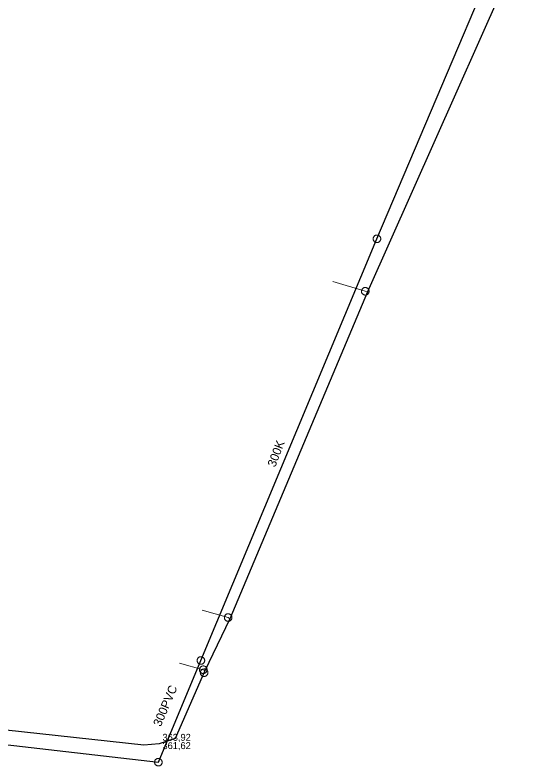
# Model space of a CAD drawing. Extents: x -741806 to -738704, y -1059275 to -1055387.
# Drawn here: x -740928.6 to -740869.8, y -1058224.8 to -1058138 of the extents above; entities that cross this region are included whole.
import ezdxf

# ---------------------------------------------------------------- set-up
doc = ezdxf.new("R2010")
doc.units = 0
doc.header["$LTSCALE"] = 0.4
for name, color, linetype, lineweight in [('2', 7, 'Continuous', 25), ('21', 7, 'Continuous', 13), ('3', 7, 'Continuous', 13), ('51', 7, 'Continuous', 13), ('52', 7, 'Continuous', 25), ('6', 7, 'Continuous', 13)]:
    doc.layers.add(name, color=color, linetype=linetype, lineweight=lineweight)
doc.layers.add('5', color=7, linetype='Continuous')

msp = doc.modelspace()

# ---------------------------------------------------------------- linework, layer by layer
at = {"layer": '2'}
for points in [[(-740907.18, -1058212.62), (-740886.85, -1058163.899), (-740866.18, -1058115.19), (-740843.879, -1058067.21), (-740824.89, -1058051.27)], [(-740986.62, -1058215.929), (-740978.449, -1058216.909), (-740964.91, -1058218.3), (-740912.09, -1058224.37), (-740907.18, -1058212.62)]]:
    msp.add_lwpolyline(points, dxfattribs=at)
at = {"layer": '21'}
for points in [[(-740887.96, -1058170.041), (-740888.199, -1058169.96), (-740891.956, -1058168.844)], [(-740903.829, -1058207.8), (-740904.028, -1058207.656), (-740907.026, -1058206.804)], [(-740906.688, -1058213.771), (-740906.906, -1058213.688), (-740909.64, -1058212.922)]]:
    msp.add_lwpolyline(points, dxfattribs=at)
at = {"layer": '3'}
for points in [[(-740886.689, -1058163.491), (-740886.732, -1058163.477), (-740886.776, -1058163.467), (-740886.822, -1058163.462), (-740886.867, -1058163.462), (-740886.913, -1058163.466), (-740886.959, -1058163.475), (-740887.002, -1058163.489), (-740887.044, -1058163.507), (-740887.083, -1058163.53), (-740887.121, -1058163.557), (-740887.155, -1058163.587), (-740887.187, -1058163.621), (-740887.213, -1058163.658), (-740887.237, -1058163.697), (-740887.256, -1058163.739), (-740887.271, -1058163.782), (-740887.28, -1058163.827), (-740887.286, -1058163.872), (-740887.285, -1058163.918), (-740887.281, -1058163.964), (-740887.272, -1058164.009), (-740887.258, -1058164.051), (-740887.24, -1058164.094), (-740887.218, -1058164.134), (-740887.191, -1058164.172), (-740887.16, -1058164.205), (-740887.127, -1058164.236), (-740887.089, -1058164.264), (-740887.05, -1058164.287), (-740887.008, -1058164.306), (-740886.965, -1058164.32), (-740886.921, -1058164.33), (-740886.875, -1058164.336), (-740886.828, -1058164.336), (-740886.784, -1058164.332), (-740886.738, -1058164.323), (-740886.695, -1058164.308), (-740886.653, -1058164.29), (-740886.614, -1058164.267), (-740886.576, -1058164.241), (-740886.542, -1058164.211), (-740886.51, -1058164.177), (-740886.483, -1058164.14), (-740886.46, -1058164.101), (-740886.441, -1058164.059), (-740886.426, -1058164.015), (-740886.416, -1058163.971), (-740886.412, -1058163.926), (-740886.412, -1058163.879), (-740886.416, -1058163.834), (-740886.426, -1058163.789), (-740886.438, -1058163.745), (-740886.457, -1058163.703), (-740886.479, -1058163.664), (-740886.507, -1058163.626), (-740886.537, -1058163.592), (-740886.57, -1058163.561), (-740886.608, -1058163.534), (-740886.647, -1058163.511), (-740886.688, -1058163.491)], [(-740907.019, -1058212.212), (-740907.062, -1058212.198), (-740907.106, -1058212.188), (-740907.152, -1058212.183), (-740907.197, -1058212.183), (-740907.243, -1058212.187), (-740907.289, -1058212.196), (-740907.332, -1058212.21), (-740907.374, -1058212.228), (-740907.413, -1058212.251), (-740907.451, -1058212.278), (-740907.485, -1058212.308), (-740907.517, -1058212.342), (-740907.543, -1058212.379), (-740907.567, -1058212.418), (-740907.586, -1058212.46), (-740907.601, -1058212.503), (-740907.61, -1058212.548), (-740907.616, -1058212.593), (-740907.615, -1058212.639), (-740907.611, -1058212.685), (-740907.602, -1058212.73), (-740907.588, -1058212.772), (-740907.57, -1058212.815), (-740907.548, -1058212.855), (-740907.521, -1058212.893), (-740907.49, -1058212.926), (-740907.457, -1058212.957), (-740907.419, -1058212.985), (-740907.38, -1058213.008), (-740907.338, -1058213.027), (-740907.295, -1058213.041), (-740907.251, -1058213.051), (-740907.205, -1058213.057), (-740907.158, -1058213.057), (-740907.114, -1058213.053), (-740907.068, -1058213.044), (-740907.025, -1058213.029), (-740906.983, -1058213.011), (-740906.944, -1058212.988), (-740906.906, -1058212.962), (-740906.872, -1058212.932), (-740906.84, -1058212.898), (-740906.813, -1058212.861), (-740906.79, -1058212.822), (-740906.771, -1058212.78), (-740906.756, -1058212.736), (-740906.746, -1058212.692), (-740906.742, -1058212.647), (-740906.742, -1058212.6), (-740906.746, -1058212.555), (-740906.756, -1058212.51), (-740906.768, -1058212.466), (-740906.787, -1058212.424), (-740906.809, -1058212.385), (-740906.837, -1058212.347), (-740906.867, -1058212.313), (-740906.9, -1058212.282), (-740906.938, -1058212.255), (-740906.977, -1058212.232), (-740907.018, -1058212.212)], [(-740911.654, -1058224.42), (-740911.652, -1058224.375), (-740911.654, -1058224.329), (-740911.661, -1058224.283), (-740911.672, -1058224.24), (-740911.688, -1058224.197), (-740911.709, -1058224.155), (-740911.733, -1058224.117), (-740911.761, -1058224.081), (-740911.794, -1058224.049), (-740911.829, -1058224.019), (-740911.867, -1058223.994), (-740911.908, -1058223.972), (-740911.95, -1058223.956), (-740911.994, -1058223.943), (-740912.04, -1058223.936), (-740912.086, -1058223.933), (-740912.131, -1058223.935), (-740912.176, -1058223.941), (-740912.221, -1058223.953), (-740912.264, -1058223.969), (-740912.305, -1058223.99), (-740912.343, -1058224.014), (-740912.379, -1058224.043), (-740912.412, -1058224.074), (-740912.441, -1058224.11), (-740912.466, -1058224.149), (-740912.487, -1058224.188), (-740912.504, -1058224.232), (-740912.517, -1058224.276), (-740912.524, -1058224.321), (-740912.527, -1058224.366), (-740912.525, -1058224.412), (-740912.518, -1058224.458), (-740912.506, -1058224.502), (-740912.491, -1058224.544), (-740912.471, -1058224.586), (-740912.446, -1058224.624), (-740912.417, -1058224.661), (-740912.385, -1058224.692), (-740912.35, -1058224.722), (-740912.312, -1058224.747), (-740912.271, -1058224.769), (-740912.229, -1058224.786), (-740912.185, -1058224.798), (-740912.14, -1058224.805), (-740912.094, -1058224.808), (-740912.048, -1058224.807), (-740912.003, -1058224.8), (-740911.958, -1058224.788), (-740911.915, -1058224.772), (-740911.875, -1058224.751), (-740911.836, -1058224.727), (-740911.8, -1058224.698), (-740911.767, -1058224.667), (-740911.738, -1058224.631), (-740911.712, -1058224.592), (-740911.692, -1058224.553), (-740911.675, -1058224.509), (-740911.663, -1058224.465), (-740911.655, -1058224.421)]]:
    msp.add_lwpolyline(points, dxfattribs=at)
at = {"layer": '51'}
for points in [[(-740888.612, -1058169.819), (-740888.625, -1058169.862), (-740888.633, -1058169.907), (-740888.636, -1058169.953), (-740888.634, -1058169.998), (-740888.627, -1058170.044), (-740888.616, -1058170.089), (-740888.6, -1058170.131), (-740888.58, -1058170.173), (-740888.555, -1058170.211), (-740888.527, -1058170.247), (-740888.495, -1058170.28), (-740888.46, -1058170.31), (-740888.422, -1058170.335), (-740888.382, -1058170.356), (-740888.339, -1058170.373), (-740888.294, -1058170.386), (-740888.25, -1058170.394), (-740888.204, -1058170.396), (-740888.158, -1058170.394), (-740888.112, -1058170.387), (-740888.068, -1058170.376), (-740888.025, -1058170.361), (-740887.984, -1058170.34), (-740887.946, -1058170.316), (-740887.909, -1058170.287), (-740887.876, -1058170.255), (-740887.848, -1058170.22), (-740887.822, -1058170.182), (-740887.801, -1058170.141), (-740887.783, -1058170.099), (-740887.772, -1058170.055), (-740887.764, -1058170.01), (-740887.761, -1058169.964), (-740887.762, -1058169.919), (-740887.769, -1058169.873), (-740887.78, -1058169.828), (-740887.796, -1058169.786), (-740887.816, -1058169.744), (-740887.841, -1058169.706), (-740887.869, -1058169.67), (-740887.901, -1058169.637), (-740887.937, -1058169.607), (-740887.975, -1058169.583), (-740888.015, -1058169.561), (-740888.058, -1058169.544), (-740888.102, -1058169.531), (-740888.147, -1058169.524), (-740888.192, -1058169.521), (-740888.239, -1058169.523), (-740888.284, -1058169.53), (-740888.328, -1058169.541), (-740888.371, -1058169.556), (-740888.412, -1058169.577), (-740888.451, -1058169.601), (-740888.487, -1058169.63), (-740888.52, -1058169.662), (-740888.549, -1058169.697), (-740888.574, -1058169.735), (-740888.596, -1058169.776), (-740888.612, -1058169.818)], [(-740904.19, -1058208.061), (-740904.147, -1058208.076), (-740904.103, -1058208.086), (-740904.057, -1058208.092), (-740904.012, -1058208.092), (-740903.966, -1058208.088), (-740903.92, -1058208.079), (-740903.877, -1058208.065), (-740903.834, -1058208.048), (-740903.795, -1058208.025), (-740903.758, -1058207.999), (-740903.723, -1058207.968), (-740903.691, -1058207.935), (-740903.664, -1058207.898), (-740903.641, -1058207.859), (-740903.622, -1058207.817), (-740903.607, -1058207.774), (-740903.597, -1058207.729), (-740903.592, -1058207.684), (-740903.591, -1058207.638), (-740903.596, -1058207.592), (-740903.605, -1058207.547), (-740903.618, -1058207.503), (-740903.636, -1058207.461), (-740903.658, -1058207.422), (-740903.685, -1058207.384), (-740903.715, -1058207.349), (-740903.749, -1058207.319), (-740903.786, -1058207.291), (-740903.825, -1058207.268), (-740903.867, -1058207.248), (-740903.91, -1058207.234), (-740903.954, -1058207.224), (-740904, -1058207.219), (-740904.045, -1058207.218), (-740904.091, -1058207.222), (-740904.137, -1058207.231), (-740904.18, -1058207.245), (-740904.222, -1058207.262), (-740904.262, -1058207.286), (-740904.299, -1058207.312), (-740904.334, -1058207.342), (-740904.365, -1058207.376), (-740904.392, -1058207.412), (-740904.416, -1058207.451), (-740904.435, -1058207.493), (-740904.45, -1058207.537), (-740904.459, -1058207.581), (-740904.465, -1058207.626), (-740904.465, -1058207.673), (-740904.461, -1058207.718), (-740904.452, -1058207.763), (-740904.439, -1058207.807), (-740904.42, -1058207.849), (-740904.399, -1058207.889), (-740904.372, -1058207.926), (-740904.341, -1058207.961), (-740904.308, -1058207.991), (-740904.271, -1058208.019), (-740904.232, -1058208.042), (-740904.191, -1058208.061)], [(-740907.312, -1058213.527), (-740907.327, -1058213.57), (-740907.337, -1058213.614), (-740907.342, -1058213.66), (-740907.342, -1058213.705), (-740907.338, -1058213.751), (-740907.329, -1058213.796), (-740907.315, -1058213.84), (-740907.297, -1058213.882), (-740907.274, -1058213.921), (-740907.248, -1058213.959), (-740907.217, -1058213.993), (-740907.183, -1058214.025), (-740907.147, -1058214.052), (-740907.108, -1058214.075), (-740907.065, -1058214.094), (-740907.022, -1058214.109), (-740906.977, -1058214.119), (-740906.932, -1058214.124), (-740906.886, -1058214.124), (-740906.84, -1058214.119), (-740906.796, -1058214.11), (-740906.752, -1058214.097), (-740906.71, -1058214.078), (-740906.67, -1058214.056), (-740906.633, -1058214.029), (-740906.598, -1058213.998), (-740906.568, -1058213.965), (-740906.54, -1058213.928), (-740906.517, -1058213.888), (-740906.497, -1058213.847), (-740906.484, -1058213.804), (-740906.474, -1058213.759), (-740906.468, -1058213.713), (-740906.468, -1058213.668), (-740906.472, -1058213.622), (-740906.481, -1058213.577), (-740906.496, -1058213.533), (-740906.513, -1058213.491), (-740906.536, -1058213.452), (-740906.563, -1058213.415), (-740906.593, -1058213.38), (-740906.627, -1058213.349), (-740906.664, -1058213.322), (-740906.703, -1058213.298), (-740906.745, -1058213.279), (-740906.788, -1058213.265), (-740906.833, -1058213.255), (-740906.878, -1058213.25), (-740906.924, -1058213.25), (-740906.97, -1058213.254), (-740907.015, -1058213.263), (-740907.058, -1058213.276), (-740907.1, -1058213.295), (-740907.14, -1058213.317), (-740907.178, -1058213.344), (-740907.212, -1058213.375), (-740907.243, -1058213.408), (-740907.27, -1058213.446), (-740907.293, -1058213.485), (-740907.312, -1058213.526)], [(-740906.983, -1058214.434), (-740906.941, -1058214.45), (-740906.897, -1058214.461), (-740906.851, -1058214.468), (-740906.807, -1058214.471), (-740906.761, -1058214.468), (-740906.715, -1058214.461), (-740906.671, -1058214.448), (-740906.628, -1058214.432), (-740906.588, -1058214.41), (-740906.55, -1058214.386), (-740906.514, -1058214.357), (-740906.481, -1058214.324), (-740906.453, -1058214.289), (-740906.428, -1058214.25), (-740906.408, -1058214.209), (-740906.391, -1058214.166), (-740906.379, -1058214.122), (-740906.373, -1058214.077), (-740906.371, -1058214.031), (-740906.374, -1058213.985), (-740906.381, -1058213.94), (-740906.393, -1058213.895), (-740906.41, -1058213.853), (-740906.43, -1058213.812), (-740906.456, -1058213.774), (-740906.485, -1058213.738), (-740906.517, -1058213.707), (-740906.554, -1058213.677), (-740906.592, -1058213.653), (-740906.633, -1058213.632), (-740906.675, -1058213.616), (-740906.719, -1058213.605), (-740906.765, -1058213.598), (-740906.81, -1058213.595), (-740906.856, -1058213.598), (-740906.902, -1058213.605), (-740906.946, -1058213.618), (-740906.989, -1058213.634), (-740907.029, -1058213.656), (-740907.067, -1058213.681), (-740907.103, -1058213.71), (-740907.136, -1058213.742), (-740907.163, -1058213.778), (-740907.189, -1058213.816), (-740907.209, -1058213.857), (-740907.226, -1058213.9), (-740907.236, -1058213.945), (-740907.244, -1058213.989), (-740907.246, -1058214.036), (-740907.243, -1058214.082), (-740907.235, -1058214.126), (-740907.224, -1058214.171), (-740907.207, -1058214.213), (-740907.186, -1058214.254), (-740907.161, -1058214.292), (-740907.132, -1058214.328), (-740907.1, -1058214.36), (-740907.063, -1058214.389), (-740907.025, -1058214.413), (-740906.984, -1058214.433)]]:
    msp.add_lwpolyline(points, dxfattribs=at)
at = {"layer": '52'}
for points in [[(-740626.537, -1058069.271), (-740626.965, -1058069.033), (-740656.548, -1058067.382), (-740672.59, -1058065.485), (-740708.822, -1058062.591), (-740710.671, -1058062.095), (-740751.42, -1058058.46), (-740773.993, -1058056.467), (-740779.522, -1058055.831), (-740794.666, -1058054.688), (-740823.883, -1058052.338), (-740835.024, -1058060.166), (-740841.695, -1058066.003), (-740887.96, -1058170.041), (-740903.829, -1058207.8), (-740906.75, -1058213.899)], [(-740906.75, -1058213.899), (-740910.14, -1058221.629), (-740912.01, -1058222.23), (-740913.75, -1058222.409), (-740969.949, -1058216.28), (-740973.57, -1058215.899), (-740981.35, -1058215.159), (-740984.02, -1058215.02)]]:
    msp.add_lwpolyline(points, dxfattribs=at)

# ---------------------------------------------------------------- texts
at = {"layer": '5'}
for s, rotation, p in [('300K', 69, (-740898.603, -1058190.348)), ('300PVC', 67, (-740911.817, -1058220.334))]:
    msp.add_text(s, height=1, rotation=rotation, dxfattribs=at).set_placement(p)
at = {"layer": '6'}
for s, p in [('363,92', (-740911.617, -1058221.896)), ('361,62', (-740911.617, -1058222.856))]:
    msp.add_text(s, height=0.8, dxfattribs=at).set_placement(p)

doc.saveas('drawing.dxf')
